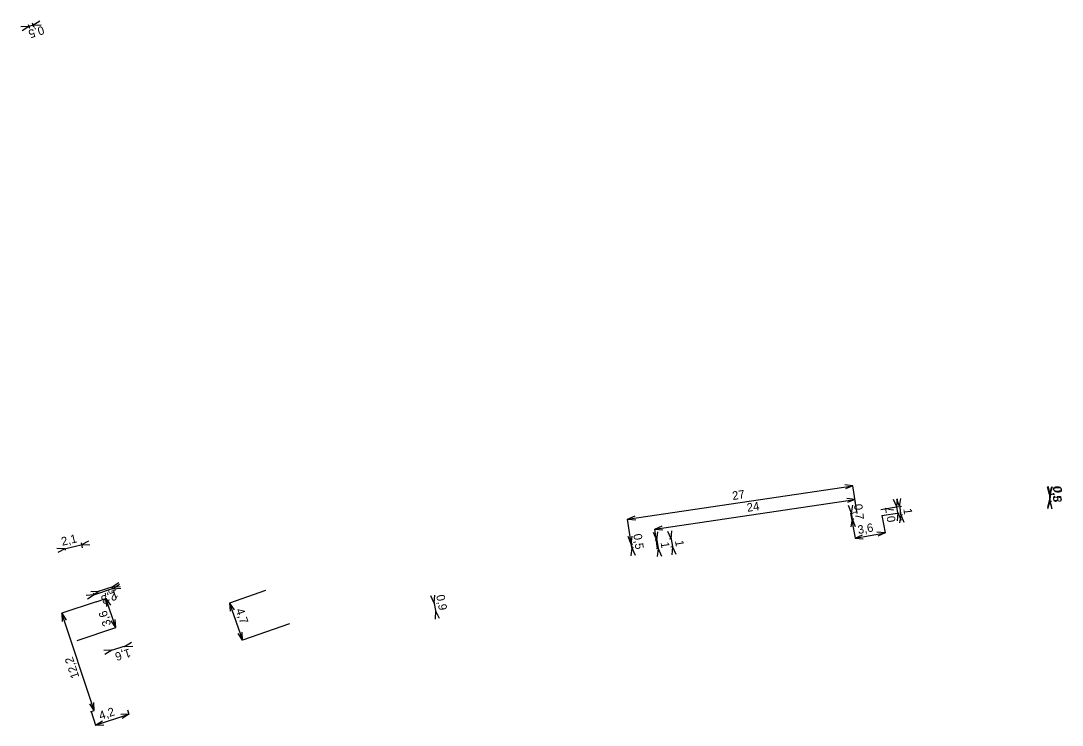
# Model space of a CAD drawing. Extents: x -740617 to -740493, y -1046794 to -1046326.
# Drawn here: x -740616.8 to -740493.3, y -1046794.5 to -1046710.9 of the extents above; entities that cross this region are included whole.
import ezdxf

# ---------------------------------------------------------------- set-up
doc = ezdxf.new("R2010")
doc.units = 0
doc.layers.add('Kota_NN', color=7, linetype='Continuous')
doc.layers.add('Kota_VN', color=7, linetype='Continuous')

msp = doc.modelspace()

# ---------------------------------------------------------------- linework, layer by layer
at = {"layer": 'Kota_NN'}
for p, q in [((-740544.81, -1046770.02), (-740518.08, -1046766.07)), ((-740518.08, -1046766.07), (-740519.04, -1046765.96)), ((-740518.08, -1046766.07), (-740518.97, -1046766.45)), ((-740517.6, -1046769.35), (-740518.08, -1046766.07)), ((-740494.75, -1046767.13), (-740494.99, -1046766.2)), ((-740494.75, -1046766.93), (-740494.76, -1046767.87)), ((-740494.75, -1046767.13), (-740494.49, -1046766.2)), ((-740541.6, -1046771.21), (-740517.84, -1046767.69)), ((-740517.84, -1046767.69), (-740518.8, -1046767.58)), ((-740517.84, -1046767.69), (-740518.73, -1046768.07)), ((-740517.6, -1046769.35), (-740517.84, -1046767.69)), ((-740512.88, -1046768.57), (-740513.28, -1046767.69)), ((-740512.88, -1046768.57), (-740512.79, -1046767.61)), ((-740494.76, -1046767.67), (-740495.02, -1046768.6)), ((-740494.76, -1046767.67), (-740494.76, -1046767.67)), ((-740494.76, -1046767.67), (-740494.52, -1046768.6)), ((-740494.75, -1046767.13), (-740494.75, -1046767.13)), ((-740518.36, -1046769.32), (-740517.83, -1046772.28)), ((-740514.76, -1046768.88), (-740512.69, -1046768.54)), ((-740514.64, -1046769.61), (-740512.56, -1046769.27)), ((-740512.73, -1046769.49), (-740512.92, -1046768.37)), ((-740512.76, -1046769.3), (-740512.85, -1046770.25)), ((-740512.76, -1046769.3), (-740512.36, -1046770.17)), ((-740544.81, -1046770.02), (-740543.93, -1046769.64)), ((-740544.3, -1046773.43), (-740544.81, -1046770.02)), ((-740544.81, -1046770.02), (-740543.85, -1046770.13)), ((-740514.64, -1046769.61), (-740514.27, -1046771.65)), ((-740544.38, -1046772.99), (-740544.27, -1046772.04)), ((-740541.34, -1046772.51), (-740541.73, -1046771.63)), ((-740541.6, -1046771.21), (-740540.72, -1046770.82)), ((-740541.26, -1046773.53), (-740541.6, -1046771.21)), ((-740541.6, -1046771.21), (-740540.65, -1046771.32)), ((-740541.34, -1046772.51), (-740541.23, -1046771.55)), ((-740517.83, -1046772.28), (-740514.27, -1046771.65)), ((-740517.83, -1046772.28), (-740516.96, -1046771.88)), ((-740514.27, -1046771.65), (-740515.23, -1046771.57)), ((-740514.27, -1046771.65), (-740515.14, -1046772.06)), ((-740544.38, -1046772.99), (-740544.76, -1046772.11)), ((-740544.41, -1046772.79), (-740544.28, -1046773.64)), ((-740544.41, -1046773), (-740544.18, -1046772.96)), ((-740541.33, -1046772.51), (-740541.54, -1046772.54)), ((-740541.37, -1046772.31), (-740541.17, -1046773.72)), ((-740517.83, -1046772.28), (-740516.87, -1046772.37)), ((-740544.31, -1046773.44), (-740544.42, -1046774.39)), ((-740544.34, -1046773.44), (-740544.11, -1046773.41)), ((-740544.31, -1046773.44), (-740543.93, -1046774.32)), ((-740541.18, -1046773.52), (-740541.39, -1046773.56)), ((-740541.2, -1046773.53), (-740541.31, -1046774.48)), ((-740541.2, -1046773.53), (-740540.81, -1046774.41)), ((-740605.77, -1046778.02), (-740607.73, -1046778.67)), ((-740605.96, -1046778.08), (-740605.16, -1046777.55)), ((-740605.96, -1046778.08), (-740605, -1046778.02)), ((-740605.96, -1046778.08), (-740605.96, -1046778.08)), ((-740607.55, -1046778.6), (-740608.5, -1046778.66)), ((-740607.55, -1046778.6), (-740608.35, -1046779.13)), ((-740607.85, -1046779.83), (-740606.7, -1046779.44)), ((-740607.55, -1046778.6), (-740607.55, -1046778.6)), ((-740605.54, -1046782.9), (-740606.7, -1046779.44)), ((-740606.7, -1046779.44), (-740606.17, -1046780.24)), ((-740606.7, -1046779.44), (-740606.64, -1046780.4)), ((-740587.79, -1046778.49), (-740592.05, -1046779.99)), ((-740567.76, -1046780.01), (-740568.17, -1046779.14)), ((-740567.76, -1046780.01), (-740567.69, -1046779.05)), ((-740592.05, -1046779.99), (-740590.49, -1046784.4)), ((-740592.05, -1046779.99), (-740591.5, -1046780.78)), ((-740592.05, -1046779.99), (-740591.97, -1046780.95)), ((-740567.8, -1046779.81), (-740567.55, -1046781.12)), ((-740567.76, -1046780.01), (-740567.76, -1046780.01)), ((-740567.59, -1046780.92), (-740567.66, -1046781.88)), ((-740567.59, -1046780.92), (-740567.59, -1046780.92)), ((-740567.59, -1046780.92), (-740567.17, -1046781.79)), ((-740610.13, -1046784.44), (-740605.54, -1046782.9)), ((-740605.54, -1046782.9), (-740606.07, -1046782.1)), ((-740605.54, -1046782.9), (-740605.6, -1046781.94)), ((-740584.91, -1046782.44), (-740590.49, -1046784.4)), ((-740590.49, -1046784.4), (-740591.03, -1046783.61)), ((-740590.49, -1046784.4), (-740590.56, -1046783.44)), ((-740606, -1046785.58), (-740606.96, -1046785.61)), ((-740606, -1046785.58), (-740606.82, -1046786.09)), ((-740604.3, -1046785.06), (-740606.19, -1046785.64)), ((-740606, -1046785.58), (-740606, -1046785.58)), ((-740604.49, -1046785.12), (-740603.67, -1046784.61)), ((-740604.49, -1046785.12), (-740603.53, -1046785.09)), ((-740604.49, -1046785.12), (-740604.49, -1046785.12)), ((-740608.46, -1046792.86), (-740607.93, -1046794.46)), ((-740604.16, -1046792.63), (-740603.98, -1046793.16)), ((-740607.93, -1046794.46), (-740603.98, -1046793.16)), ((-740607.93, -1046794.46), (-740607.13, -1046793.94)), ((-740603.98, -1046793.16), (-740604.94, -1046793.21)), ((-740603.98, -1046793.16), (-740604.79, -1046793.69)), ((-740607.93, -1046794.46), (-740606.97, -1046794.41))]:
    msp.add_line(p, q, dxfattribs=at)
at = {"layer": 'Kota_VN'}
for p, q in [((-740615.17, -1046711.4), (-740616.03, -1046711.67)), ((-740615.92, -1046711.37), (-740615.78, -1046711.8)), ((-740615.45, -1046711.19), (-740615.3, -1046711.65)), ((-740615.36, -1046711.46), (-740614.55, -1046710.94)), ((-740615.36, -1046711.46), (-740614.4, -1046711.42)), ((-740615.84, -1046711.61), (-740616.8, -1046711.65)), ((-740615.84, -1046711.61), (-740616.65, -1046712.12)), ((-740494.7, -1046767.09), (-740494.92, -1046766.16)), ((-740494.69, -1046766.9), (-740494.72, -1046768.09)), ((-740494.7, -1046767.09), (-740494.42, -1046766.17)), ((-740494.7, -1046767.09), (-740494.5, -1046767.1)), ((-740512.54, -1046768.54), (-740512.89, -1046767.65)), ((-740512.54, -1046768.54), (-740512.4, -1046767.59)), ((-740494.72, -1046767.89), (-740494.99, -1046768.81)), ((-740494.73, -1046767.89), (-740494.52, -1046767.9)), ((-740494.72, -1046767.89), (-740494.5, -1046768.83)), ((-740518.26, -1046769.31), (-740518.61, -1046768.41)), ((-740518.28, -1046769.11), (-740518.16, -1046770.21)), ((-740518.27, -1046769.31), (-740518.06, -1046769.28)), ((-740518.26, -1046769.31), (-740518.11, -1046768.36)), ((-740512.56, -1046768.34), (-740512.4, -1046769.71)), ((-740512.42, -1046769.51), (-740512.56, -1046770.46)), ((-740512.55, -1046768.54), (-740512.34, -1046768.51)), ((-740512.43, -1046769.51), (-740512.22, -1046769.48)), ((-740512.42, -1046769.51), (-740512.06, -1046770.4)), ((-740518.18, -1046770.01), (-740518.32, -1046770.96)), ((-740518.19, -1046770.01), (-740517.98, -1046769.98)), ((-740518.18, -1046770.01), (-740517.83, -1046770.9)), ((-740539.65, -1046772.38), (-740540.05, -1046771.5)), ((-740539.65, -1046772.38), (-740539.56, -1046771.42)), ((-740611.78, -1046773.59), (-740609.37, -1046773.01)), ((-740609.47, -1046773.43), (-740609.61, -1046772.86)), ((-740609.56, -1046773.06), (-740608.72, -1046772.6)), ((-740609.56, -1046773.06), (-740608.6, -1046773.08)), ((-740539.64, -1046772.38), (-740539.84, -1046772.41)), ((-740539.68, -1046772.18), (-740539.45, -1046773.52)), ((-740611.58, -1046773.54), (-740612.54, -1046773.51)), ((-740611.58, -1046773.54), (-740612.43, -1046774)), ((-740611.58, -1046773.53), (-740611.54, -1046773.73)), ((-740539.47, -1046773.32), (-740539.68, -1046773.36)), ((-740539.48, -1046773.32), (-740539.57, -1046774.28)), ((-740539.48, -1046773.32), (-740539.08, -1046774.19)), ((-740605.71, -1046778.21), (-740608.3, -1046779.08)), ((-740605.9, -1046778.28), (-740605.96, -1046778.09)), ((-740605.9, -1046778.28), (-740605.1, -1046777.75)), ((-740605.9, -1046778.28), (-740604.94, -1046778.22)), ((-740608.11, -1046779.01), (-740609.07, -1046779.07)), ((-740608.11, -1046779.01), (-740608.91, -1046779.54)), ((-740608.1, -1046779.02), (-740608.17, -1046778.82)), ((-740607.85, -1046779.83), (-740611.94, -1046781.2)), ((-740608.09, -1046792.73), (-740611.94, -1046781.2)), ((-740611.94, -1046781.2), (-740611.41, -1046782)), ((-740611.94, -1046781.2), (-740611.88, -1046782.16)), ((-740608.09, -1046792.73), (-740608.15, -1046791.78)), ((-740608.09, -1046792.73), (-740608.62, -1046791.93)), ((-740608.53, -1046792.88), (-740608.09, -1046792.73))]:
    msp.add_line(p, q, dxfattribs=at)

# ---------------------------------------------------------------- texts
at = {"layer": 'Kota_NN'}
for s, rotation, p in [('27', 8.4106, (-740532.33, -1046767.77)), ('0,5', 269.4048, (-740494.34, -1046766.08)), ('24', 8.4111, (-740530.6, -1046769.17)), ('0,7', 99.4537, (-740513, -1046770.31)), ('3,6', 10.1029, (-740517.43, -1046771.81)), ('0,5', 278.3901, (-740544.14, -1046771.84)), ('1', 278.3802, (-740540.9, -1046772.8)), ('1,7', 198.324, (-740605.45, -1046778.33)), ('0,9', 280.6312, (-740567.53, -1046779.09)), ('3,6', 108.5822, (-740606.07, -1046782.55)), ('4,7', 289.4137, (-740591.33, -1046780.81)), ('1,6', 196.9713, (-740603.94, -1046785.37)), ('4,2', 18.3219, (-740607.34, -1046793.85))]:
    msp.add_text(s, height=1, rotation=rotation, dxfattribs=at).set_placement(p)
at = {"layer": 'Kota_VN'}
for s, rotation, p in [('0,5', 197.4982, (-740614.22, -1046711.52)), ('0,8', 268.3812, (-740494.27, -1046766.18)), ('0,7', 276.3677, (-740517.97, -1046768.29)), ('1', 276.8775, (-740512.1, -1046768.81)), ('2,1', 13.4618, (-740611.88, -1046773.2)), ('1', 279.8925, (-740539.2, -1046772.62)), ('2,3', 198.5137, (-740605.62, -1046778.6)), ('12,2', 108.4827, (-740609.84, -1046788.74))]:
    msp.add_text(s, height=1, rotation=rotation, dxfattribs=at).set_placement(p)

doc.saveas('drawing.dxf')
